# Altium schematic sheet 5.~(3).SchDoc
size 420 x 297 mm
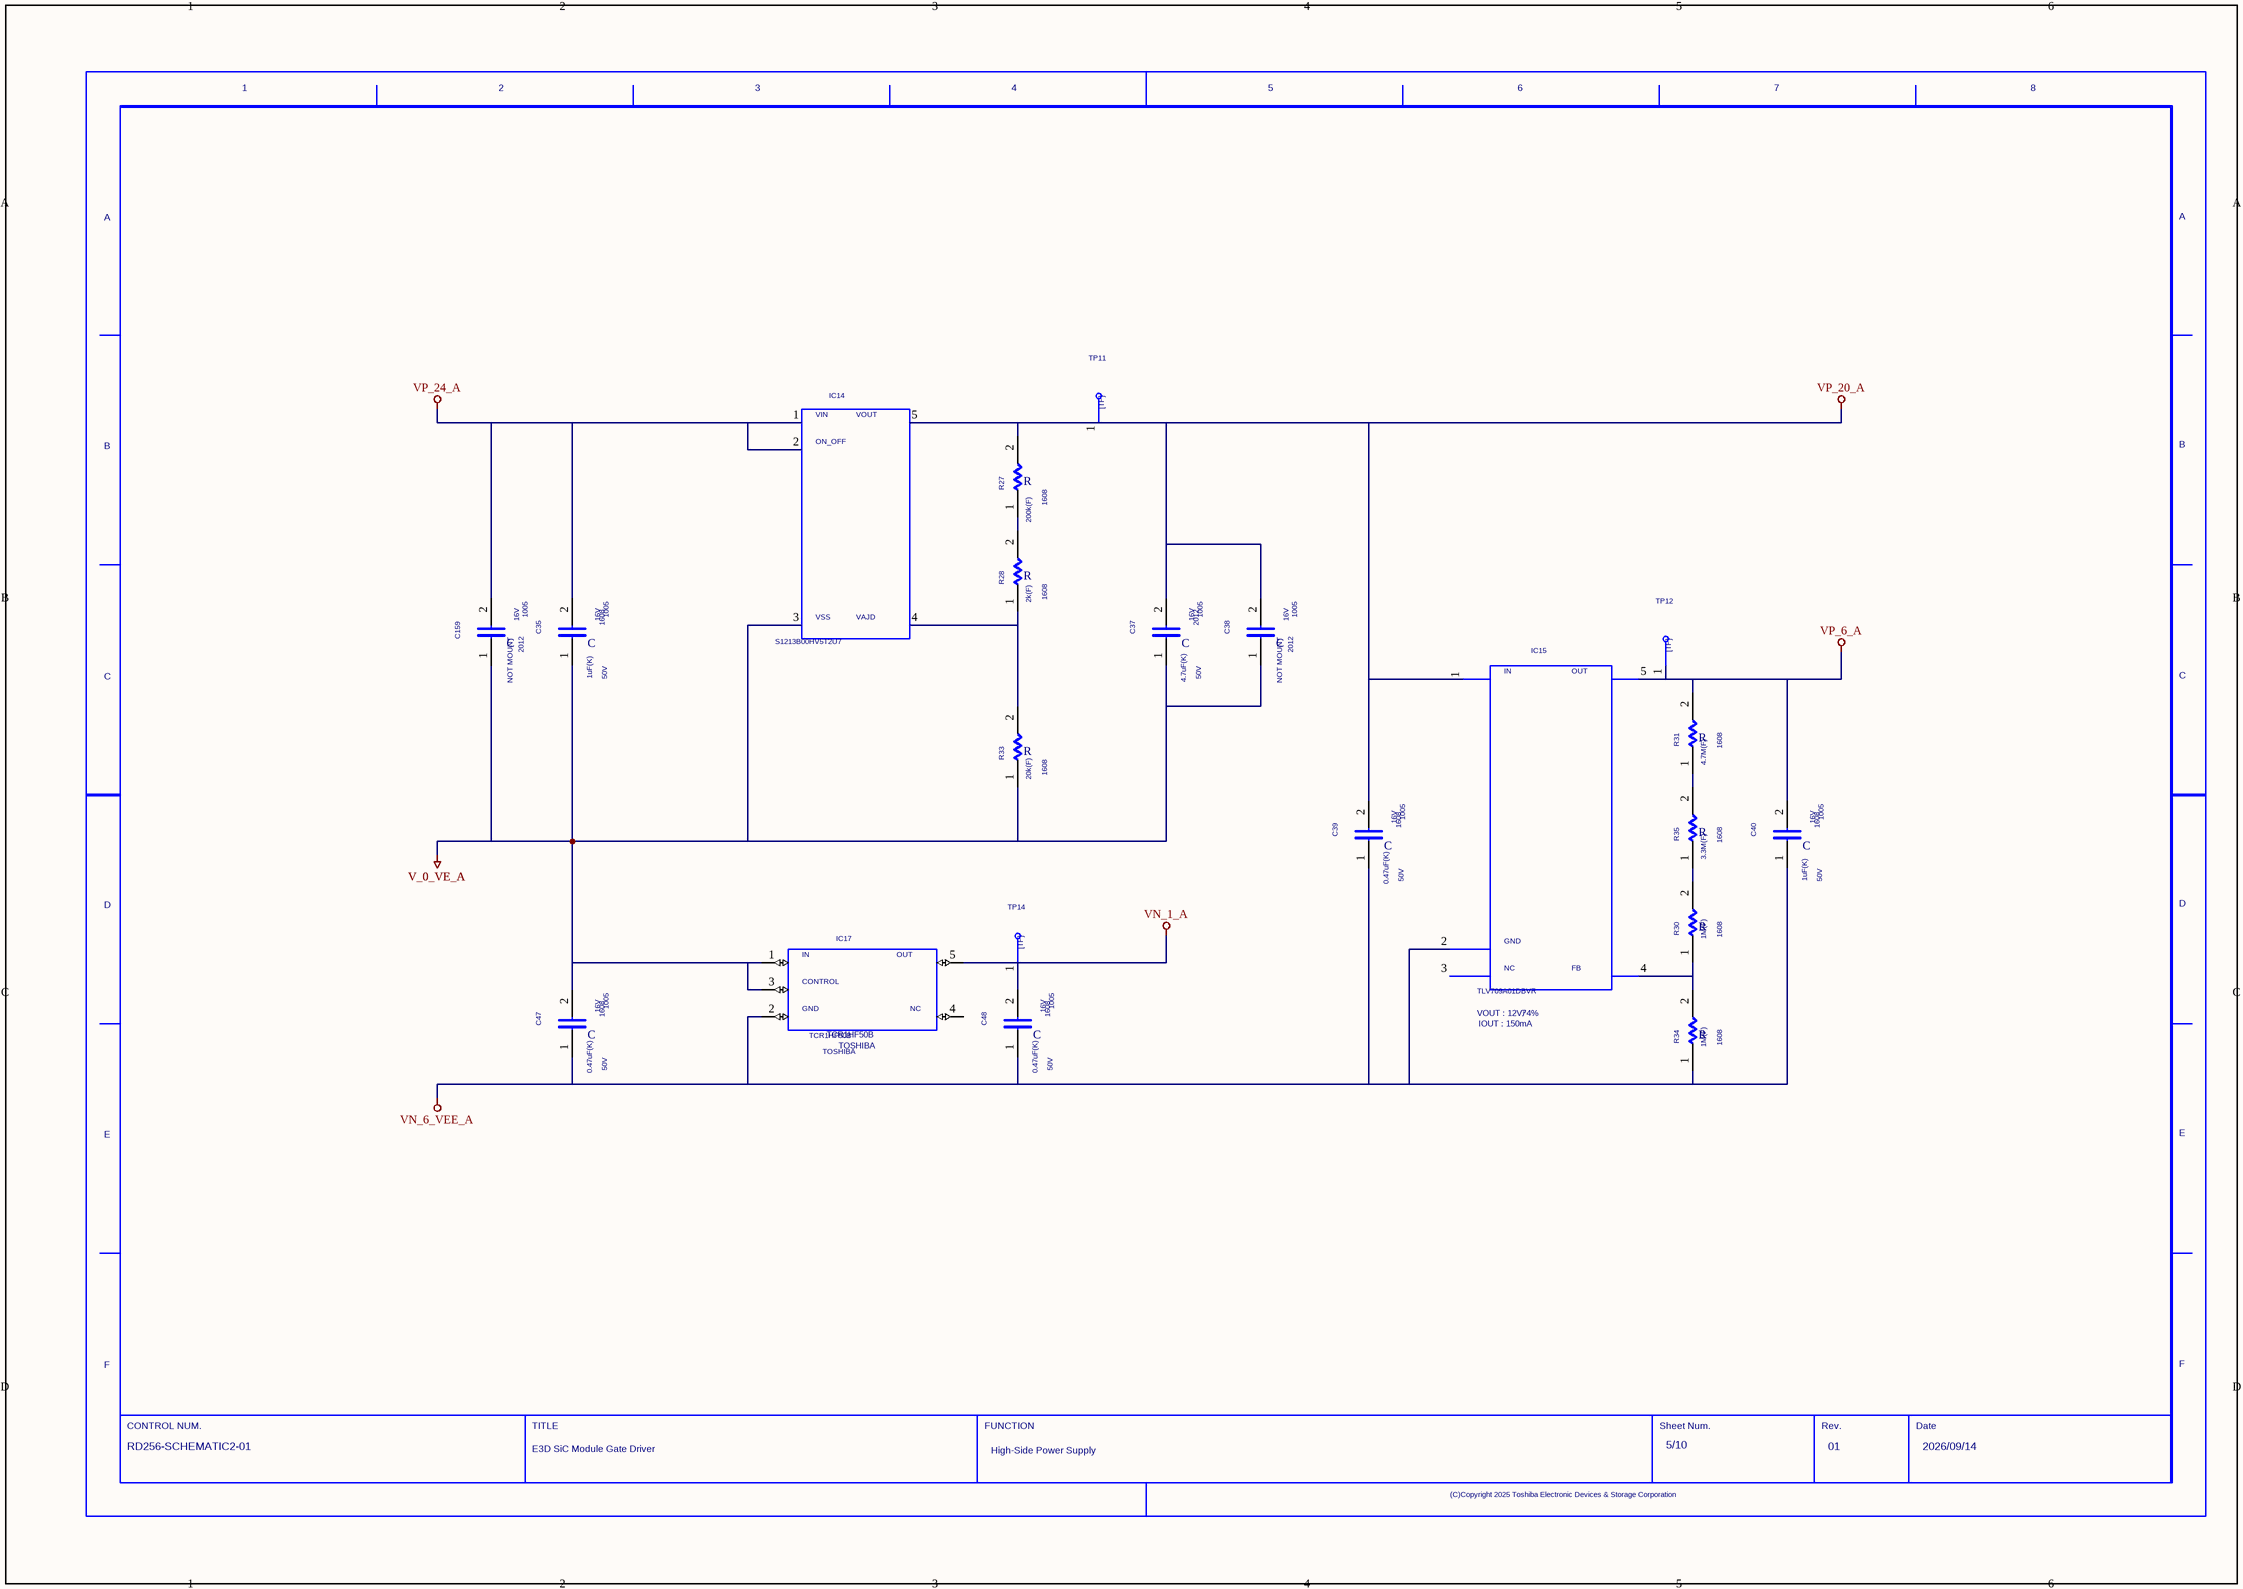
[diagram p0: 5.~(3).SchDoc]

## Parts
C35  VOLTAGE: 16V  CODE: 1005  VAL1: 1uF(K)  VAL2: 50V  SIZECODESMD: 1608  (hidden comment: C)
C37  VOLTAGE: 16V  CODE: 1005  VAL1: 4.7uF(K)  VAL2: 50V  SIZECODESMD: 2012  (hidden comment: C)
C38  VOLTAGE: 16V  CODE: 1005  SIZECODESMD: 2012  NOTMOUNT: NOT MOUNT  (hidden comment: C)
C39  VOLTAGE: 16V  CODE: 1005  VAL1: 0.47uF(K)  VAL2: 50V  SIZECODESMD: 1608  (hidden comment: C)
C40  VOLTAGE: 16V  CODE: 1005  VAL1: 1uF(K)  VAL2: 50V  SIZECODESMD: 1608  (hidden comment: C)
C47  VOLTAGE: 16V  CODE: 1005  VAL1: 0.47uF(K)  VAL2: 50V  SIZECODESMD: 1608  (hidden comment: C)
C48  VOLTAGE: 16V  CODE: 1005  VAL1: 0.47uF(K)  VAL2: 50V  SIZECODESMD: 1608  (hidden comment: C)
C159  VOLTAGE: 16V  CODE: 1005  SIZECODESMD: 2012  NOTMOUNT: NOT MOUNT  (hidden comment: C)
IC14  S1213B00HV5T2U7
IC15  CLASS: IOUT : 150mA  NC: VOUT : 12Vｱ4%  VAL3: TLV709A01DBVR  (hidden comment: TLV709)
IC17  TCR1HF50B  VENDOR: TOSHIBA
R27  VAL1: 200k(F)  SIZECODESMD: 1608  (hidden comment: R)
R28  VAL1: 2k(F)  SIZECODESMD: 1608  (hidden comment: R)
R30  VAL1: 1M(F)  SIZECODESMD: 1608  (hidden comment: R)
R31  VAL1: 4.7M(F)  SIZECODESMD: 1608  (hidden comment: R)
R33  VAL1: 20k(F)  SIZECODESMD: 1608  (hidden comment: R)
R34  VAL1: 1M(F)  SIZECODESMD: 1608  (hidden comment: R)
R35  VAL1: 3.3M(F)  SIZECODESMD: 1608  (hidden comment: R)
TP11  TP  (value not drawn)
TP12  TP  (value not drawn)
TP14  TP  (value not drawn)
U?  REVISION: 01  SHEETNUMBER: 5/10  FUNCTION: High-Side Power Supply  TITLE: E3D SiC Module Gate Driver  DRAWINGNUMBER: RD256-SCHEMATIC2-01  DATE: 2026/09/14  (hidden comment: WAKU_DEF100)

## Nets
V_0_VE_A: C35.1 C37.1 C38.1 C47.2 C159.1 IC14.3 IC17.1 IC17.3 R33.1
VN_1_A: C48.2 IC17.5 TP14.1
VN_6_VEE_A: C39.1 C40.1 C47.1 C48.1 IC15.2 IC17.2 R34.1
VP_6_A: C40.2 IC15.5 R31.2 TP12.1
VP_20_A: C37.2 C38.2 C39.2 IC14.5 IC15.1 R27.2 TP11.1
VP_24_A: C35.2 C159.2 IC14.1 IC14.2
SIG00045: R27.1 R28.2
SIG00046: IC14.4 R28.1 R33.2
SIG00047: IC15.4 R30.1 R34.2
SIG00048: R30.2 R35.1
SIG00049: R31.1 R35.2

Not connected (* = marked no-connect by the designer): IC15 3; IC17 4

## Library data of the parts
C35 C37-C40 C47 C48 C159 = C: ORIGINALSYMBOLORIGIN: (0,0); VC2: 0; PSPICETEMPLATE: C^@REFDES %1 %2 ?TOLERANCE¦C^@REFDES¦ @VALUE ?IC/IC=@IC/ TC=@TC1,@TC2 ?TOLERANCE¦\n.model C^@REFDES CAP C=1 DEV=@TOLERANCE% TC1=@TC1 TC2=@TC2 VC1=@VC1 VC2=@VC2¦; SAVECOUNT: 2; UPDATETIME: 08:48:12; UPDATEUSER: HP_Z8_KEYSHOT; INSTANCENAME: INS2266227
IC14 = S1213B00HV5T2U7: OriginalSymbolOrigin: (0,0); PSPICETEMPLATE: X^@REFDES %ADJUST %OUTPUT %INPUT @MODEL; SAVECOUNT: 7; UPDATETIME: 09:48:38; UPDATEUSER: t5459927; TIME: 08:48:13; INSTANCENAME: INS2266489
IC15 = TLV709: OriginalSymbolOrigin: (0,0); PSPICETEMPLATE: X^@REFDES %IN %GND %NC %FB %OUT @MODEL; SAVECOUNT: 5; UPDATETIME: 10:01:49; UPDATEUSER: t5459927; TIME: 08:48:16; INSTANCENAME: INS2266385
IC17 = TCR1HF50B: OriginalSymbolOrigin: (-2540,0); PSPICETEMPLATE: X^@REFDES %IN %GND %CONTROL %NC %OUT @MODEL; SAVECOUNT: 4; UPDATETIME: 10:27:35; UPDATEUSER: t5459927; TIME: 11:54:59; INSTANCENAME: INS2266087
R27 R28 R30 R31 R33-R35 = R: ORIGINALSYMBOLORIGIN: (0,0); PSPICETEMPLATE: R^@REFDES %1 %2 ?TOLERANCE¦R^@REFDES¦ @VALUE TC=@TC1,@TC2 ?TOLERANCE¦\n.model R^@REFDES RES R=1 DEV=@TOLERANCE% TC1=@TC1 TC2=@TC2¦; TC2: 0; VAL2: 100mW; SAVECOUNT: 2; UPDATETIME: 08:48:13; UPDATEUSER: HP_Z8_KEYSHOT; INSTANCENAME: INS2266059
TP11 = TP: ORIGINALSYMBOLORIGIN: (0,0); SAVEAREA0: -242,-92,12810,7836; SAVECOUNT: 2; UPDATETIME: 16:18:11; UPDATEUSER: fukuda-y; TIME: 16:12:21; INSTANCENAME: INS2266317
TP12 = TP: ORIGINALSYMBOLORIGIN: (0,0); SAVEAREA0: -242,-92,12810,7836; SAVECOUNT: 2; UPDATETIME: 16:18:11; UPDATEUSER: fukuda-y; TIME: 16:12:21; INSTANCENAME: INS2266305
TP14 = TP: ORIGINALSYMBOLORIGIN: (0,0); SAVEAREA0: -242,-92,12810,7836; SAVECOUNT: 2; UPDATETIME: 16:18:11; UPDATEUSER: fukuda-y; TIME: 16:12:21; INSTANCENAME: INS2266293
U? = WAKU_DEF100: OriginalSymbolOrigin: (10160,284480); SAVECOUNT: 4; UPDATETIME: 11:30:53; UPDATEUSER: t5459927; TIME: 14:30:25; SAVEAREA0: -63393,-16950,474261,314592; PLOTTIME: HH:MM; SHTSAVECOUNT: 21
